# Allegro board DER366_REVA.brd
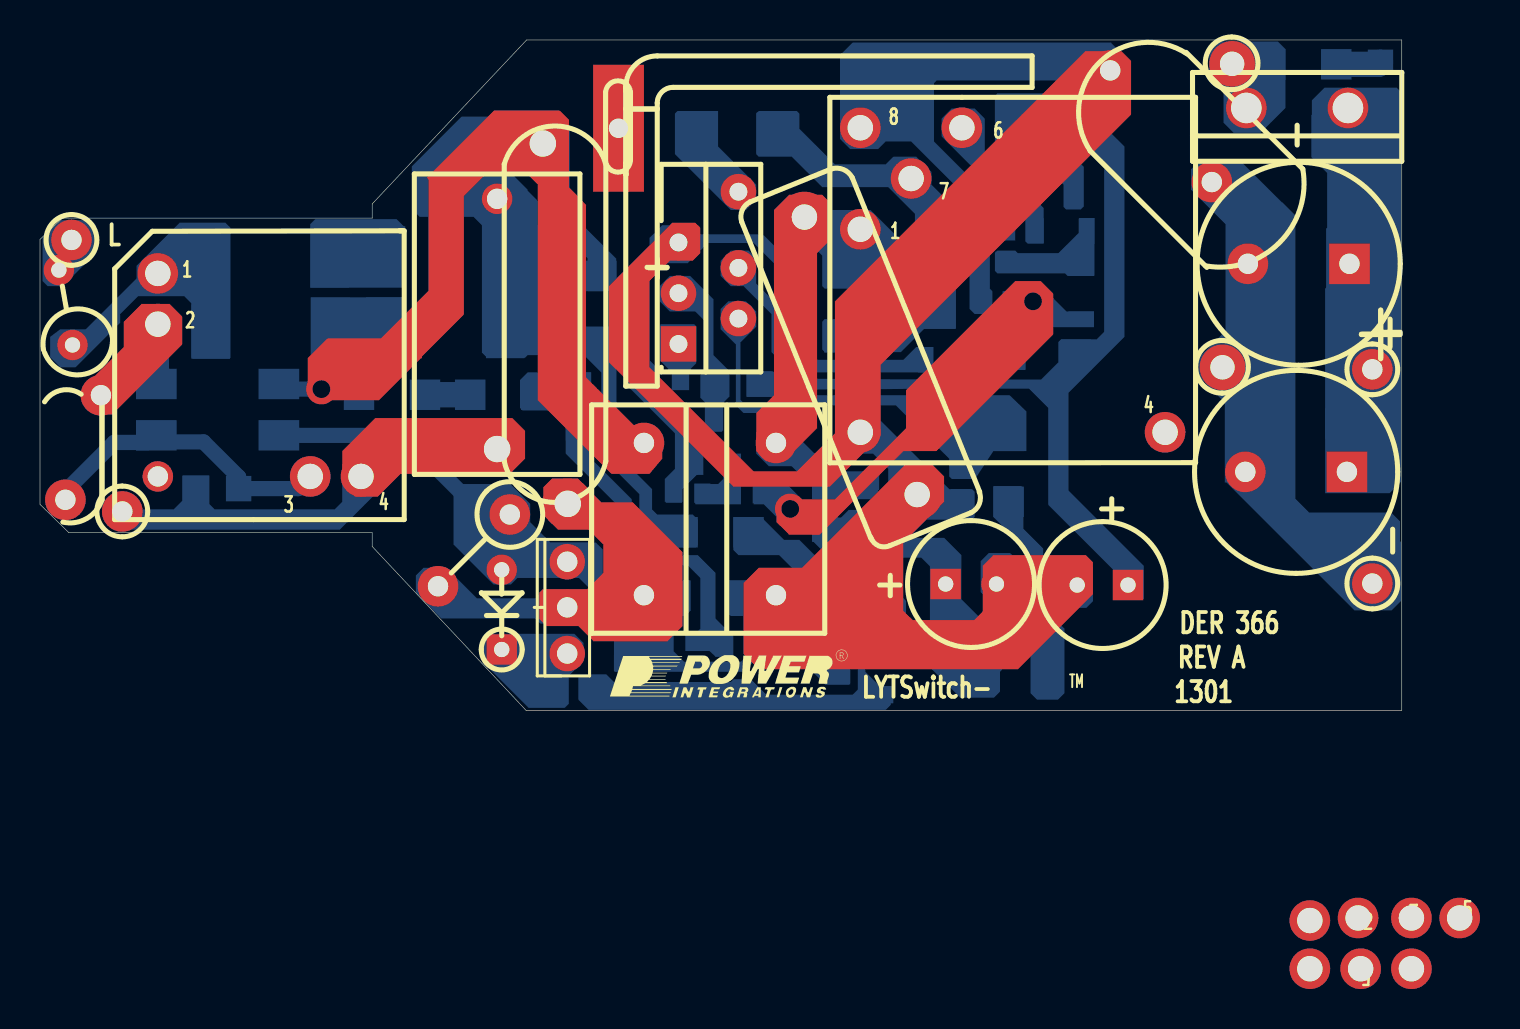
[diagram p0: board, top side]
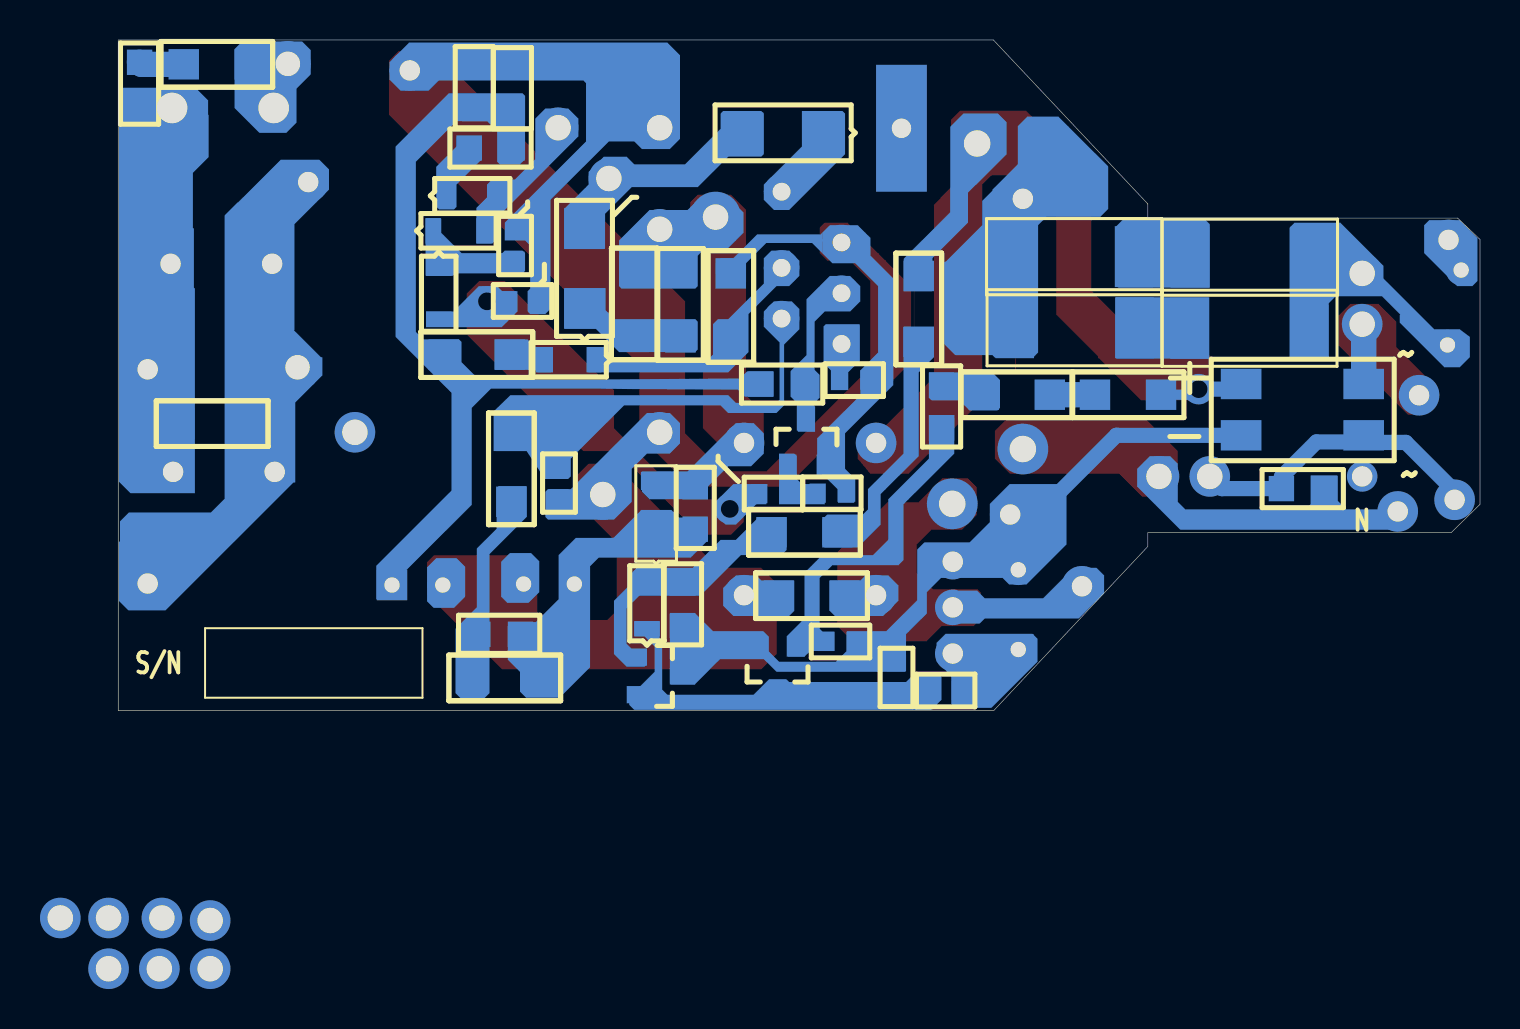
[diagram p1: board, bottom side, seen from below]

Outline 68.1 x 33.55 mm; copper layers: TOP, BOTTOM. Coordinates in mm from the lower left corner of the outline.
Outline path: 0,23.57 1.12,24.64 16.61,24.64 16.61,25.35 24.33,33.55 68.1,33.55 68.1,0 24.31,0 16.61,8.2 16.61,8.89 1.45,8.89 0,10.31 0,23.57

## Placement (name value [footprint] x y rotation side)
BR1  B10S-G  [PISMSOIC4]  5.82 13.77 90 bottom
C1  220 nF  [PI_NP_XCAP_RAD550X330LS493D040]  22.86 13.08 90 top
C2  47 pF  [PISMC0805]  26.92 16.28 270 bottom
C3  10 nF  [PISMC0603]  29.18 0.94 90 bottom
C4  120 nF  [PINPCR730X200LS590D40]  25.76 27.33 270 top
C5  220 nF  [PINPCAPRAD730X230590050]  38.23 24.69 292.1 top
C6  2.2 uF  [PIPOLCAPCYLD250LS100030]  45.29 6.32 0 top
C7  2.2 nF  [PISMC1206]  39.98 21.97 270 bottom
C8  47 uF  [PISMC1206]  37.47 18.57 90 bottom
C9  56 uF  [PIPOLCAPCYLD250LS100030]  54.41 6.27 180 top
C10  10 nF  [PISMC0603]  33.12 10.87 180 bottom
C11  100 nF  [PISMC0805]  48.39 30.07 90 bottom
C12  100 nF  [PISMC0603]  48.26 22.56 90 bottom
C13  100 pF  [PISMC0805]  67.03 32.44 270 bottom
C14  330 uF  [PIPOLCAPCYLD400LS200040]  65.48 22.35 180 top
C15  330 uF  [PIPOLCAPCYLD400LS200040]  65.35 11.94 180 top
C16  47 pF  [PISMC0805]  47.98 3.81 0 bottom
CY1  470 pF  [PINPCAPRAD394X275394030]  53.52 32.03 315 top
D1  BAV21WS-7-F  [PISMSOD323]  41.66 4.09 90 bottom
D2  DFLU1400-7  [PISMDDFLR120012]  41.2 8.84 270 bottom
D3  US1J  [PISMDSMA]  44.78 20.12 90 bottom
D4  US1D  [PISMDSMA]  32.84 28.91 0 bottom
D5  BAV16WS-7-F  [PISMSOD323]  44.3 17.55 0 bottom
D6  BAV21WS-7-F  [PISMSOD323]  51.66 25.76 180 bottom
D7  BAV21WS-7-F  [PISMSOD323]  52.35 24 180 bottom
D8  BYW29-200  [PIDVT0220ACREVA]  60.33 30.15 0 top
F1  5 A  [PI_V_AXIAL_160LS150D030]  1.63 18.29 100.3 top
FL1  PCB Terminal 22 AWG  [PI_HOLE_22AWG]  59.61 32.36 0 top
FL2  PCB Terminal 22 AWG  [PI_HOLE_22AWG]  59.13 17.17 0 top
HS1  HEATSINK,FAB, eSIP WITH BRKT, DER350, PI CUST  [PI_HSK_DER350_ESIP]  29.29 16.23 0 top
L1  RM5  [PI_BOBBIN_RM5_6P_CLP]  5.89 21.87 180 top
L2  5 mH  [PIIND4P615X420LS350X270040]  30.2 13.36 0 top
NOREF  -  []  0 10.31 0 top
NOREF#2  -  []  -224.79 -136.63 0 top
NOREF#3  -  []  68.1 0 90 top
NOREF#4  -  []  -146.97 62.39 0 top
NOREF#5  -  []  28.5 0.63 0 top
Q1  MMBT3906  [PISMSOT23132]  42.16 0.79 270 bottom
Q2  MMBT4401LT1G  [PISMSOT23132]  36.07 3.2 0 bottom
Q3  IRFU320PBF  [PI_TO251AA_123]  26.37 2.87 90 top
Q4  MMBT3904  [PISMSOT23132]  32.74 12.29 180 bottom
R1  510  [PISMR2512]  14.5 22.68 180 bottom
R2  510  [PISMR2512]  23.29 22.71 180 bottom
R3  12 k  [PISMR0805]  7.8 11.1 0 bottom
R4  1 M  [PISMR1206]  28.07 18.44 90 bottom
R5  1 M  [PISMR1206]  35.43 8.92 180 bottom
R6  2.4 M  [PISMR0805]  39.88 6.38 270 bottom
R7  162 k  [PISMR1206]  15.95 15.8 0 bottom
R8  162 k  [PISMR1206]  21.51 15.8 0 bottom
R9  30.1 k  [PISMR0603]  32.69 3.45 180 bottom
R10  15  [PISMR0603]  26.01 0.99 0 bottom
R11  100  [PI12WVRESD180LS150D040]  23.5 9.8 225 top
R12  47 k  [PISMR1206]  35.08 5.74 180 bottom
R13  510 k  [PISMR0805]  39.24 11.2 270 bottom
R14  2.00 M  [PISMR1206]  47.12 1.63 0 bottom
R15  2.00 M  [PISMR1206]  48.44 10.44 90 bottom
R16  49.9 k  [PISMR0603]  46.05 12.09 270 bottom
R17  200 k  [PISMR1206]  42.29 18.69 90 bottom
R18  49.9 k  [PISMR0603]  32 16.54 180 bottom
R19  3 k  [PISMR1206]  48.51 17.81 0 bottom
R20  196 k  [PISMR0805]  33.83 16.33 0 bottom
R21  20 k  [PISMR0805]  50.29 30.12 90 bottom
R22  39  [PISMR0805]  50.55 28.14 180 bottom
R23  10  [PISMR0603]  34.62 10.85 0 bottom
R24  1 k  [PISMR0603]  48.59 20.5 180 bottom
R25  30  [PISMR1206]  64.82 32.33 180 bottom
R26  20 k  [PISMR1206]  65.05 14.35 180 bottom
R27  510  [PISMR2512]  14.53 19.13 180 bottom
R28  510  [PISMR2512]  23.27 19.15 180 bottom
RV1  250 Vac  [PIDISC350X160LS210X140040]  2.69 16.56 270 top
T1  RM7/I  [PI_BOBBIN_RM7_8P_CLP]  41.02 24.08 0 top
TP1  CON1  [PITPKEYSTONE100X100]  1.57 23.55 0 top
TP2  CON1  [PITPKEYSTONE100X100]  4.11 9.96 0 top
TP3  CON1  [PITPKEYSTONE100X100]  66.62 17.07 0 top
TP4  CON1  [PITPKEYSTONE100X100]  66.62 6.35 0 top
U1  LYT4314E  [PIICESIP76TH]  31.93 18.34 90 top
VR1  1N5245B-T  [PIDV200X080X030DO35]  23.09 3.05 90 top
VR2  MMSZ5257BS-7-F  [PISMSOD323]  52.07 22.12 270 bottom

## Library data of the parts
BR1 = DIODE BRIDGE_~~+-
C1 = CAP NP: alternate symbols: (pinpcaprad550x395490030horz)
C2-C5 C7 C8 C10-C13 C16 CY1 = CAP NP
C6 C9 = CAP POL: alternate symbols: (pipolcapcyld250ls100030h)
C14 C15 = CAP POL: alternate symbols: (pipolcapcyld400ls200040800h)
D1-D8 = DIODE
F1 = FUSE
FL1 FL2 = TERM_1Pin
HS1 = HS-PI_CUSTOM1
L1 = BRM6_6P_CLP
L2 = INDUCTOR_4P_revB
Q1 = PNP_BEC
Q2 Q4 = NPN_BEC
Q3 = FET_N_GDS
R1-R10 R12-R25 R27 R28 = R
R11 = R: alternate symbols: (pi12wvresd180ls200d040,pi12wvresd180ls250d040,pi12wresd180ls675d040)
R26 = R: tolerance: 5%
RV1 = VARISTOR
T1 = BRM7_8P_CLP
TP1-TP4 = TESTPOINT
U1 = LNK40X_eSIP
VR1 = DIODE_ZENER: alternate symbols: (pidax375x070030do35)
VR2 = DIODE_ZENER

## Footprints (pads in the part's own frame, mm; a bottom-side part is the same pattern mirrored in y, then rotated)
PI12WVRESD180LS150D040
  round 2.032 hole 1.016: 1(0,0) 2(5.08,0)
PI_BOBBIN_RM5_6P_CLP
  round 2.032 hole 1.27: 1(0,0) 2(0,2.54) 3(-7.62,10.16) 4(-10.16,10.16) 5(-57.607,34.798) 6(-60.147,34.798) CLP1(-62.687,34.798)
  round 1.524 hole 1.016: CLP2(0,10.16)
PI_BOBBIN_RM7_8P_CLP
  round 2.032 hole 1.27: 1(0,0) 2(29.972,-34.468) 3(24.892,-34.468) 4(15.24,-10.16) 5(22.479,-34.595) 6(5.08,5.08) 7(2.54,2.54) 8(0,5.08) CLP1(0,-10.16) CLP2(27.559,-34.468)
PI_HOLE_22AWG
  round 2.286 hole 1.219: 1(0,0)
PI_HSK_DER350_ESIP
  rect 2.54x6.35 hole 0.965: 1(-0.356,12.903)
PI_NP_XCAP_RAD550X330LS493D040
  round 2.54 hole 1.321: 1(0,0)
  round 1.524 hole 1.016: 2(12.522,0)
PI_TO251AA_123
  round 1.778 hole 1.016: 1(-0.025,0) 2(2.286,0) 3(4.572,0)
PI_V_AXIAL_160LS150D030
  round 1.524 hole 0.762: 1(0,0) 2(3.81,0)
PIDISC350X160LS210X140040
  round 2.032 hole 1.016: 1(0.787,0.356) 2(6.02,-1.422)
PIDV200X080X030DO35
  rect 1.524x1.524 hole 0.762: 1(0,0)
  round 1.524 hole 0.762: 2(3.988,0)
PIDVT0220ACREVA
  round 2.032 hole 1.524: 1(5.08,0) 2(0,0)
PIICESIP76TH
  rect 1.778x1.778 hole 0.889: 1(0,0)
  round 1.778 hole 0.889: 2(1.27,-2.997) 3(2.54,0) 4(3.81,-2.997) 5(5.08,0) 7(7.62,-2.997)
PIIND4P615X420LS350X270040
  round 2.032 hole 1.016: 1(0,-7.595) 2(6.604,-7.595) 3(0,0.025) 4(6.604,0.025)
PINPCAPRAD394X275394030
  round 2.032 hole 1.016: 1(0,0) 2(7.543,-0.359)
PINPCAPRAD730X230590050
  round 2.54 hole 1.27: 1(0,0) 2(14.986,0)
PINPCR730X200LS590D40
  round 2.54 hole 1.321: 1(-1.041,-0.61) 2(16.993,0.635)
PIPOLCAPCYLD250LS100030
  rect 1.524x1.524 hole 0.762: 1(0,0)
  round 1.524 hole 0.762: 2(2.54,0)
PIPOLCAPCYLD400LS200040
  rect 2.032x2.032 hole 1.016: 1(0,0)
  round 2.032 hole 1.016: 2(5.08,0)
PISMC0603
  rect 0.813x0.965 smd: 1(0,0) 2(1.422,0)
PISMC0805
  rect 1.27x1.27 smd: 1(0,0) 2(2.134,0)
PISMC1206
  rect 1.524x1.524 smd: 1(0,0) 2(3.302,0)
PISMDDFLR120012
  rect 2.286x1.524 smd: 1(-0.025,0)
  rect 0.914x1.524 smd: 2(-2.642,0)
PISMDSMA
  rect 2.032x2.032 smd: 1(0,0) 2(4.013,0)
PISMR0603
  rect 0.813x0.965 smd: 1(0,0) 2(1.422,0)
PISMR0805
  rect 1.27x1.27 smd: 1(0,0) 2(2.134,0)
PISMR1206
  rect 1.524x1.524 smd: 1(0,0) 2(3.302,0)
PISMR2512
  rect 1.93x3.048 smd: 1(0,0) 2(5.994,0)
PISMSOD323
  rect 0.762x1.27 smd: 1(0,0) 2(2.54,0)
PISMSOIC4
  rect 1.524x2.032 smd: 1(0,0) 2(2.571,0) 3(2.571,6.129) 4(0,6.129)
PISMSOT23132
  rect 0.864x1.016 smd: 1(-1.88,0) 2(0,0)
  rect 0.864x1.27 smd: 3(-0.94,2.286)
PITPKEYSTONE100X100
  round 2.032 hole 1.016: 1(0,0)

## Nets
BULK+: C5.1 C7.1 D2.2 L2.4 R13.1 R17.2 T1.1
BULK-: C5.2 C6.2 C8.2 C9.2 C10.2 C11.2 C12.2 CY1.1 L2.2 Q4.2(EMITTER) R12.1 R16.2 R18.2 R21.2 R24.2 T1.8 T1.CLP1 U1.5(S)
N2034910: C14.2 C15.2 CY1.2 FL2.1 R26.2 TP4.1
N2960943: C4.2 L2.1 Q3.2(D) R11.2 R12.2
N2960957: Q3.1(G) R10.1 VR1.1
N3477441: C9.1 C11.1 R19.2 R20.2 R21.1 R22.2
N3478377: C8.1 D5.1 U1.4(BP)
N3479119: C13.2 C14.1 C15.1 D8.1 R26.1 TP3.1
N3481544: C6.1 C16.1 D2.1 R13.2 R14.1
N3482634: R15.2 R16.1 U1.2(V)
N3538375: BR1.3 C4.1 L2.3 R4.2 R7.1
N3564395: BR1.4 C3.2 Q1.3(COLLECTOR) Q2.2(EMITTER) Q3.3(S) R6.2 R9.2 R11.1 VR1.2
N3568268: C1.1 L1.4 R3.1 TP2.1
N3576797: BR1.2 L1.2 RV1.1
N3617192: D4.1 U1.7(D)
N3617220: D3.2 D4.2 T1.7
N3617246: C7.2 D3.1 R17.1
N3624850: R18.1 U1.1(R)
N3624949: Q4.3(COLLECTOR) R20.1 U1.3(FB)
N3631334: D8.2 FL1.1 R25.2
N3631358: C13.1 R25.1
N3634006: C10.1 Q4.1(BASE) R23.1
N3634524: R23.2 R24.1 VR2.2
N3634757: C12.1 D7.1 VR2.1
N3672532: BR1.1 L1.3 R3.2 RV1.2
N3672946: F1.1 L1.1 R1.2 R27.2
N3675846: C3.1 D1.1 Q1.2(EMITTER) Q2.3(COLLECTOR) R10.2
N3676738: D1.2 Q1.1(BASE) R5.1 R6.1
N3678831: D5.2 R19.1
N3689416: F1.2 TP1.1
N3689420: R1.1 R2.2
N3689424: C1.2 R2.1 R28.1
N3690239: R4.1 R5.2
N3694128: R7.2 R8.1
N3694132: C2.1 R8.2
N3694136: C2.2 Q2.1(BASE) R9.1
N3695980: C16.2 R14.2 R15.1
N3696337: D6.2 D7.2 T1.6
N3706359: D6.1 R22.1
N3724230: R27.1 R28.2

Pads without a net: HS1 1; L1 5 6 CLP1 CLP2; T1 2 3 4 5 CLP2

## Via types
v1: diameter 1.524, hole 0.889, TOP to BOTTOM, 5 vias

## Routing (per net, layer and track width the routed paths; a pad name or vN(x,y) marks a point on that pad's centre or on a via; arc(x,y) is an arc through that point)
BULK+: length 12.9
  BOTTOM w0.127: C7.1 42.29,21.97 R17.2 42.29,22.81 T1.1 38.53,24.08 ; L2.4 37.19,13.39 39.24,11.33 R13.1 39.52,11.48 D2.2
BULK-: length 59.6
  TOP w0.508: T1.CLP1 41.02,13.74
  BOTTOM w0.127: R16.2 44.09,10.67 43.69,11.07 43.69,11.25 T1.CLP1 ; 32.44,23.52 34.34,23.52 34.35,23.53 35.5,23.53 35.52,23.51 35.95,23.51 37.47,22 C8.2 ; C10.2 31.7,11.15 32.74,12.19 Q4.2 32.74,13.51 30.58,15.67 R18.2 30.48,16.41 29.72,17.17 29.72,21.21 v1(31.93,23.42) ; CY1.1 53.29,32.26 R21.2 50.24,32.21 C11.2 43.1,32.21 41.02,30.12 T1.8 43.36,29.16 48.26,24.26 C12.2 47.55,23.98 47.17,23.6 R24.2 ; R12.1 36.78,5.74 L2.2
  BOTTOM w0.381: v1(31.93,23.42) 32,23.42 ; 32,23.42 32.26,23.42 32.49,23.65 ; 32,23.42 32.26,23.67 32.41,23.52 32.42,23.53 32.44,23.52
  BOTTOM w0.508: v1(31.93,23.42) 32.18,23.67 32.26,23.67
N2034910: length 11.9
  BOTTOM w0.508: C15.2 61.7,10.52 ; FL2.1 60.88,17.17 61.32,16.74 61.32,14.78 R26.2 61.75,14.45
  BOTTOM w1.27: C14.2 60.4,24.64 CY1.2
N2960943: length 8.5
  BOTTOM w0.127: R11.2 20.18,6.21 21.26,5.13 25.58,5.13 Q3.2 ; 31.78,5.74 30.23,5.74 v1(30.2,5.77)
N2960957: length 5.9
  BOTTOM w0.127: VR1.1 23.24,2.9 Q3.1 ; R10.1 26.01,2.49 Q3.1 ; Q3.1 26.09,3.33
N3477441: length 35.5
  BOTTOM w0.127: 53.47,19.43 53.47,28.04 51.38,30.12 R21.1 48.44,30.12 C11.1 48.39,27.97 R22.2 ; R20.2 50.34,16.33 R19.2
  BOTTOM w1.27: R19.2 51.82,17.22 50.7,16.1
N3478377: length 12.3
  BOTTOM w0.127: D5.1 44.14,17.5 43.41,17.5 43.21,17.3 38.38,17.3 37.47,18.21 C8.1 37.34,18.69 37.34,19.58 34.92,22 34.92,22.15
N3479119: length 11.4
  BOTTOM w1.27: C13.2 65.56,30.3 D8.1 65.41,20.45
N3481544: length 9.7
  BOTTOM w0.127: R14.1 47.98,2.49 C16.1 47.75,3.58 47.09,3.58 45.29,5.38 C6.1 ; 41.83,8.86 D2.1 39.34,8.86 R13.2
N3482634: length 22.3
  BOTTOM w0.127: R15.2 48.34,13.64 48.24,13.64 48.19,13.59 ; R15.2 47.7,13.74 R16.1 45.97,12.17 ; R15.2 46.66,15.52 37.78,15.52 37.34,15.07 35.27,15.07 34.9,15.44 34.9,17.15 34.92,17.17 34.92,19.61
N3538375: length 10.2
  TOP w0.127: 24.64,28.88 23.09,28.88
  TOP w0.508: 29.69,13.39 L2.3
  TOP w1.27: 24.64,28.88 C4.1
  BOTTOM w0.508: 27.28,23.42 27.64,23.06 27.64,21.74 R4.2 ; R7.1 14.35,15.8 v1(14.07,16.08) ; C4.1 25.96,27.99
  BOTTOM w0.762: v1(14.07,16.08) 12.2,16.08 BR1.3
N3564395: length 38.7
  BOTTOM w0.127: 39.88,4.09 38.99,3.2 Q2.2 35.05,2.18 30.35,2.18 30.18,2.36 ; 39.88,4.09 Q1.3 ; 39.88,4.09 R6.2 ; Q3.3 27.91,5.89 27.91,5.41 29.18,4.14 C3.2 30.18,2.36 ; Q3.3 26.75,7.49 ; Q3.3 23.55,7.49 23.5,7.44 ; 30.18,2.36 R9.2 ; VR1.2 23.5,7.44 ; 23.5,7.44 R11.1
  BOTTOM w0.762: BR1.4 18.19,13.77 21.29,10.67
N3568268: length 16.3
  BOTTOM w0.127: TP2.1 4.17,9.96 4.75,9.37 ; TP2.1 4.47,9.6 6.93,9.6 7.8,10.46 8.64,9.63 14.76,9.63 16.05,10.92 L1.4 ; TP2.1 4.11,9.91 4.57,9.45
  BOTTOM w0.508: R3.1 7.8,10.46
N3576797: length 3
  BOTTOM w1.27: BR1.2 5.82,19.25 L1.2
N3617192: length 3.9
  BOTTOM w0.127: D4.1 32.84,27.89 34.77,25.96 34.92,25.96
N3617220: length 10.8
  BOTTOM w0.127: D3.2 44.91,24.21 43.56,25.55 T1.7 39.14,26.62 D4.2
N3617246: length 5.3
  BOTTOM w0.127: C7.2 R17.1 42.67,18.69 43.94,19.96 D3.1
N3624850: length 1.8
  BOTTOM w0.127: U1.1 31.95,18.31 31.95,16.59 R18.1
N3624949: length 7.4
  BOTTOM w0.127: Q4.3 33.83,14.73 R20.1 33.43,16.74 33.43,19.79 32.33,20.88 U1.3
N3631334: length 4.4
  BOTTOM w1.27: 59.64,32.33 FL1.1 ; 59.64,32.33 R25.2 ; 59.64,32.33 60.33,31.65 D8.2
N3631358: length 2.3
  BOTTOM w1.27: R25.1 66.93,32.33 C13.1
N3634006: length 3
  BOTTOM w0.127: Q4.1 R23.1 33.17,10.85 C10.1
N3634524: length 2.9
  BOTTOM w0.127: v1(37.52,10.08) 36.75,10.85 R23.2 ; R24.1 48.62,20.47 v1(49.66,20.47)
N3634757: length 6.3
  BOTTOM w0.127: VR2.1 52.17,23.7 ; 52.17,23.7 D7.1 ; 52.17,23.7 51.03,22.56 C12.1
N3672532: length 15.5
  BOTTOM w0.762: L1.3 12.9,11.1 R3.2 9.93,11.68 8.18,13.44 6.15,13.44 BR1.1 5.46,13.41 3.71,13.41 1.27,10.97 RV1.2
N3672946: length 9.9
  BOTTOM w0.127: F1.1 2.39,18.36 L1.1 6.32,22.3
  BOTTOM w1.27: R1.2 8.51,19.15 R27.2
N3675846: length 18.6
  BOTTOM w0.127: 27.84,0.94 C3.1 35.1,0.94 Q2.3 35.43,0.91 35.94,0.41 41.78,0.41 Q1.2 41.15,1.8 41.15,3.33 41.66,3.84 D1.1
N3678831: length 0.3
  BOTTOM w0.127: 46.99,17.81 D5.2
N3689416: length 1.8
  BOTTOM w0.127: TP1.1 1.57,22.67 F1.2
N3689424: length 4.6
  BOTTOM w0.127: 23.14,25.32 C1.2
  BOTTOM w1.27: R2.1 23.22,18.82 R28.1
N3690239: length 11.8
  BOTTOM w0.127: R4.1 28.32,18.19 28.32,12.85 30.23,10.95 30.23,9.86 31.17,8.92 R5.2
N3694128: length 2.3
  BOTTOM w1.27: R8.1 R7.2
N3694136: length 6.1
  BOTTOM w0.127: Q2.1 33.93,3.45 R9.1 ; 29.21,10.57 26.92,12.85 C2.2
N3695980: length 9.6
  BOTTOM w0.127: R15.1 48.44,9.35 49.91,7.87 49.91,4.01 C16.2 50.42,3.51 R14.2
N3696337: length 6.9
  BOTTOM w0.127: T1.6 46.61,28.65 46.61,27.84 48.49,25.96 48.92,25.96 D6.2 49.73,25.15 D7.2
N3706359: length 2.9
  BOTTOM w0.127: D6.1 51.66,27.03 R22.1
N3724230: length 2.7
  BOTTOM w1.27: R27.1 16.87,19.13 R28.2

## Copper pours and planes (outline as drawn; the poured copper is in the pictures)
BULK+ on TOP (solid shape): 39.5,25.43 39.5,23.52 38.86,22.89 38.86,14.12 37.21,12.47 36.32,12.47 35.81,12.98 35.81,14.88 36.7,15.77 36.7,25.04 37.47,25.81 39.12,25.81
BULK+ on BOTTOM (solid shape): 39.62,11.96 41.91,11.96 41.91,10.95 41.53,10.57 38.61,10.57 38.61,11.2 37.59,12.22 36.45,12.22 35.81,12.85 35.81,13.87 36.32,14.38 37.21,14.38
BULK+ on BOTTOM (solid shape): 39.62,25.04 41.53,25.04 43.05,23.52 43.05,21.23 42.93,21.11 39.24,21.11 39.12,21.23 39.12,22.76 38.73,23.14 37.59,23.14 36.83,23.9 36.83,24.92 37.59,25.68 38.99,25.68
BULK- on TOP (solid shape): 54.56,32.51 54.56,29.82 42.04,17.3 42.04,13.74 39.5,11.2 34.67,11.2 28.45,17.42 28.45,21.23 31.62,24.41 32.77,24.41 33.02,24.16 33.02,22.89 32.64,22.5 31.5,22.5 30.48,21.49 30.48,17.17 35.69,11.96 37.85,11.96 39.75,13.87 39.75,20.47 52.27,32.99 54.08,32.99
BULK- on TOP (solid shape): 45.21,11.71 45.21,10.44 43.17,8.39 43.17,4.99 43.64,4.52 46.71,4.52 47.14,4.95 47.14,7.24 47.65,7.75 47.65,7.77 52.3,7.77 52.65,7.42 52.65,5.82 48.9,2.06 35.94,2.06 35.18,2.82 35.18,6.38 35.94,7.14 38.1,7.14 43.31,12.34 44.58,12.34
BULK- on BOTTOM (solid shape): 37.85,6.12 37.85,5.23 37.34,4.72 34.54,4.72 34.29,4.98 34.29,6.5 35.94,6.5 36.2,6.76 37.21,6.76
BULK- on BOTTOM (solid shape): 32.97,23.83 36.14,23.83 37.34,22.63 37.97,22.63 38.23,22.38 38.23,21.87 37.72,21.36 36.83,21.36 36.7,21.49 36.7,22.38 35.69,23.39 33.4,23.39 32.89,22.89 32.89,23.9
BULK- on BOTTOM (solid shape): 45.47,11.07 46.61,11.07 46.74,10.95 46.74,9.68 46.61,9.55 43.31,9.55 42.42,10.44 42.42,12.09 41.66,12.85 40.51,12.85 40.01,13.36 40.01,14.38 40.51,14.88 41.66,14.88
BULK- on BOTTOM (solid shape): 32.89,23.9 32.89,22.89 32.38,22.38 31.24,22.38 30.1,21.23 30.1,17.91 30.99,17.02 30.99,15.77 33.15,13.61 33.15,12.09 32.13,11.07 32.13,10.44 31.24,10.44 31.24,11.58 31.75,12.09 31.75,13.87 29.34,16.28 29.34,21.62 30.48,22.76 30.48,23.65 31.11,24.28 32.51,24.28
BULK- on BOTTOM (solid shape): 53.57,33.4 54.53,32.44 54.53,31.57 53.98,31.01 52.58,31.01 52.07,31.52 44.83,31.52 44.7,31.39 44.7,28.47 48.77,24.41 48.77,23.52 47.75,23.52 47.5,23.27 47.5,21.11 47.62,20.98 47.62,19.96 47.5,19.84 46.74,19.84 46.48,20.09 46.48,25.55 43.56,28.47 42.29,28.47 41.91,28.09 40.51,28.09 40.01,28.6 40.01,32.79 40.64,33.43 53.57,33.43
Net_1 on BOTTOM (solid shape): 48.95,7.44 48.95,5.69 48.64,5.38 47.57,5.38 47.04,5.92 47.04,7.47 47.45,7.87 48.51,7.87
Net_1 on BOTTOM (solid shape): 52.65,7.16 52.65,5.46 52.32,5.13 51.31,5.13 50.75,5.69 50.75,7.19 51.18,7.62 52.2,7.62
Net_5 on BOTTOM (solid shape): 2.79,24.28 2.79,22.89 1.14,21.23 0.38,21.23 0.13,21.49 0.13,23.65 1.02,24.54 2.54,24.54
N2034910 on BOTTOM (solid shape): 62.1,25.43 62.13,25.43 62.78,24.78 62.78,10.59 63.46,9.91 67.56,9.91 68.01,9.46 68.01,8.47 68.07,8.41 68.07,5.49 67.59,5 65.74,5 59.33,11.4 59.25,11.4 59.25,15.41 57.89,16.76 57.89,17.68 57.96,17.68 59.31,19.02 59.28,19.05 59.28,24.33 57.56,26.06 57.56,27.08 58.04,27.56 59.97,27.56
N2960943 on TOP (solid shape): 28.07,10.41 29.64,10.41 32.13,7.92 32.13,4.22 31.37,3.45 27.69,3.45 26.92,4.22 25.32,4.22 24.97,4.57 24.97,5.89 25.15,6.07 27.36,6.07 28.17,6.88 28.17,8.31 27.43,9.04 25.91,9.04 25.17,9.78 25.17,11.18 25.6,11.61 26.9,11.61
N2960943 on BOTTOM (solid shape): 30.99,6.5 32.51,6.5 32.51,4.98 32.26,4.72 29.84,4.72 29.08,5.49 29.08,6.25 29.59,6.76 30.73,6.76
N2960943 on BOTTOM (solid shape): 21.84,5.61 24.77,5.61 25.15,5.99 26.04,5.99 26.54,5.49 26.54,4.85 26.04,4.34 25.02,4.34 24.77,4.6 20.07,4.6 18.8,5.87 18.8,6.76 19.18,7.14 20.32,7.14
N2960957 on BOTTOM (solid shape): 27.18,3.38 27.18,2.46 26.44,1.73 26.44,0.33 26.24,0.13 24.43,0.13 22.12,2.44 22.12,3.58 22.38,3.84 26.72,3.84
N3477441 on BOTTOM (solid shape): 54.23,28.22 54.23,18.69 51.44,15.9 51.44,11 55.19,7.24 55.19,5.56 53.9,5.56 53.72,5.74 53.72,6.99 50.42,10.29 50.42,15.14 49.45,16.1 44.25,16.1 42.21,16.08 37.11,16.05 36.75,15.7 35.33,15.7 35.33,16.97 36.65,16.97 37.01,16.61 44.42,16.56 50.06,16.56 50.93,17.42 50.93,18.44 51.05,18.57 52.83,18.57 53.21,18.95 53.21,27.46 51.18,29.49 49.66,29.49 49.15,28.98 49.15,27.46 49.02,27.33 48.01,27.33 47.75,27.58 47.75,30.76 47.88,30.89 51.56,30.89
N3478377 on BOTTOM (solid shape): 35.81,22.63 35.81,21.36 37.59,19.58 38.1,19.58 38.35,19.33 38.35,17.81 38.61,17.55 43.18,17.55 43.81,18.19 44.58,18.19 44.65,18.11 44.65,16.99 44.58,16.92 37.59,16.92 36.58,17.93 36.58,19.84 35.18,21.23 34.54,21.23 34.04,21.74 34.04,22.5 34.54,23.01 35.43,23.01
N3479119 on BOTTOM (solid shape): 68.07,30.94 68.07,11.46 67.49,10.87 64.26,10.87 64.26,21.11 64.31,21.16 64.31,24.1 64.36,24.16 64.36,26.9 63.58,27.69 63.58,29.79 63.6,29.82 63.6,30.53 64.24,31.17 67.84,31.17
N3481544 on BOTTOM (solid shape): 43.33,8.64 45.21,8.64 46.08,7.77 46.08,5.56 47.22,4.42 48.41,4.42 48.62,4.22 48.62,2.54 48.01,1.93 48.01,0.94 47.7,0.63 46.02,0.63 44.5,2.16 44.5,7.21 44.07,7.65 39.47,7.65 38.61,8.51 38.61,9.58 38.68,9.65 40.06,9.65 40.44,10.03 41.94,10.03
N3482634 on BOTTOM (solid shape): 35.81,19.96 35.81,19.2 35.03,18.41 35.03,15.54 35.18,15.39 37.21,15.39 37.59,15.77 48.49,15.77 49.33,14.96 49.33,12.98 47.68,12.98 46.76,11.58 45.59,11.58 45.47,11.71 45.47,12.6 42.8,15.27 37.97,15.27 37.59,14.88 35.18,14.88 34.8,15.27 34.8,18.31 34.04,19.08 34.04,20.09 34.42,20.47 35.31,20.47
N3538375 on TOP (solid shape): 26.45,29.55 26.45,26.17 26.97,25.65 26.97,25.63 27.32,25.29 27.3,25.27 27.3,16.66 29.84,14.12 30.61,14.12 31.11,13.61 31.11,12.6 30.48,11.84 28.57,11.84 24.89,15.52 24.89,26.31 24.43,26.77 22.23,26.77 21.2,25.74 21.2,19.81 19.1,17.72 19.1,17.63 19.05,17.63 16.94,15.52 14,15.52 13.39,16.13 13.39,17.63 14.38,18.62 17.04,18.62 19.43,21.01 19.43,26.57 19.34,26.66 22.71,30.02 25.98,30.02
N3538375 on BOTTOM (solid shape): 26.49,29.21 26.49,24.93 28.82,22.61 28.82,20.99 28.83,20.98 27.41,20.98 27.41,22.61 25.6,24.41 25.6,25.91 23.67,27.84 23.67,29.44 24.1,29.87 25.83,29.87
N3564395 on BOTTOM (solid shape): 24.51,10.34 24.51,9.42 25.53,8.41 27.79,8.41 28.14,8.05 28.14,5.51 29.69,3.96 31.65,3.96 31.67,3.94 31.67,2.97 32.21,2.44 35.05,2.44 35.56,2.95 35.56,3.68 35.84,3.96 38.35,3.96 39.27,4.88 40.49,4.88 40.51,4.85 40.51,1.37 40.44,1.3 39.27,1.3 38,2.57 35.81,2.57 35.18,1.93 28.75,1.93 28.7,1.98 28.7,3.81 27.66,4.85 27.66,5.92 26.95,6.63 23.88,6.63 23.55,6.3 22.68,6.3 20.68,8.31 20.68,11.28 20.73,11.33 23.52,11.33
N3568268 on TOP (solid shape): 24.26,14 24.26,12.6 23.5,11.84 18.03,11.84 16.89,10.69 15.75,10.69 15.11,11.33 15.11,12.98 16.76,14.63 23.62,14.63
N3568268 on BOTTOM (solid shape): 17.14,12.09 17.14,11.2 14.99,9.04 4.06,9.04 4.06,10.06 6.68,10.06 7.11,10.49 7.11,11.73 7.14,11.76 8.46,11.76 8.47,11.75 8.47,10.33 8.74,10.06 14.73,10.06 15.11,10.44 15.11,12.34 15.49,12.73 16.51,12.73
N3576797 on TOP (solid shape): 7.11,19.71 7.11,18.31 3.61,14.81 2.74,14.81 2.74,14.83 2.11,15.47 2.11,16.13 2.51,16.54 2.54,16.54 4.19,18.19 4.19,19.46 5.08,20.35 6.48,20.35
N3617192 on BOTTOM (solid shape): 33.91,28.22 35.81,26.31 35.81,25.55 35.31,25.04 34.54,25.04 31.75,27.84 31.75,29.87 31.88,30 33.91,30
N3617220 on BOTTOM (solid shape): 37.97,29.87 37.97,29.11 39.75,27.33 42.29,27.33 42.67,27.71 43.81,27.71 44.58,26.95 44.58,26.31 45.8,25.1 45.8,23.09 43.79,23.09 43.75,23.13 43.75,24.85 42.42,26.19 39.12,26.19 37.59,27.71 35.94,27.71 35.81,27.84 35.81,29.87 35.94,30 37.85,30
N3617246 on BOTTOM (solid shape): 45.8,21.11 45.8,19.13 45.77,19.1 44.22,19.1 43.05,17.93 39.24,17.93 39.12,18.06 39.12,19.46 39.24,19.58 43.28,19.58 43.73,20.03 43.73,21.12 43.74,21.13 45.77,21.13
N3624850 on BOTTOM (solid shape): 32.82,19.23 32.82,17.37 32.46,17.02 32.46,16.03 31.62,16.03 31.6,16.05 31.6,16.92 31.01,17.5 31.01,19.3 31.04,19.33 32.72,19.33
N3624949 on BOTTOM (solid shape): 33.68,20.57 33.68,17.78 34.47,16.99 34.47,15.7 34.16,15.39 34.16,14 33.27,14 33.27,15.39 33.02,15.65 33.02,16.79 33.27,17.04 33.27,19.46 32.77,19.96 31.5,19.96 30.99,20.47 30.99,21.23 31.5,21.74 32.51,21.74
N3631334 on BOTTOM (solid shape): 62.28,33.1 62.28,30.15 61.04,28.91 59.69,28.91 59.18,29.41 59.18,31.12 58.47,31.83 58.47,33.05 58.9,33.48 61.9,33.48
N3634006 on BOTTOM (solid shape): 35.05,10.31 32.77,10.31 32.77,11.33 33.91,11.33 34.16,11.58 34.16,12.73 34.29,12.85 35.05,12.85
N3634524 on TOP (solid shape): 50.67,20.85 50.67,18.82 44.83,12.98 43.18,12.98 38.99,8.79 37.47,8.79 36.83,9.42 36.83,10.31 37.34,10.82 37.59,10.82 37.85,10.57 39.75,10.57 43.31,14.12 43.31,16.03 48.77,21.49 50.04,21.49
N3634524 on BOTTOM (solid shape): 38.23,10.44 38.23,9.8 37.72,9.3 37.21,9.3 36.2,10.31 35.69,10.31 35.69,11.33 37.34,11.33
N3634524 on BOTTOM (solid shape): 51.33,19.96 52.7,19.96 52.7,19.46 52.68,19.46 52.7,19.43 52.7,19.18 48.92,19.18 48.13,19.96 48.13,20.98 48.9,20.98 49.15,21.23 50.06,21.23
N3634757 on BOTTOM (solid shape): 52.73,21.77 52.7,21.74 51.38,21.74 51.26,21.87 47.88,21.87 47.75,22 47.75,22.89 47.88,23.01 48.77,23.01 48.9,22.89 50.93,22.89 51.94,23.9 51.94,24.61 51.97,24.64 52.73,24.64
N3672946 on BOTTOM (solid shape): 9.53,24.16 9.53,17.65 9.47,17.6 7.65,17.6 7.57,17.68 7.57,20.29 7.59,20.32 7.59,20.35 7.21,20.73 4.9,20.73 3.99,19.81 4.01,19.79 4.01,19.41 1.78,17.17 1.02,17.17 0.51,17.68 0.51,18.69 1.02,19.08 2.29,19.08 4.83,21.62 4.83,22.25 6.99,24.41 9.27,24.41
N3675846 on BOTTOM (solid shape): 42.29,3.71 41.78,3.71 41.27,3.2 41.27,1.93 42.04,1.17 42.16,1.17 42.55,0.79 42.55,0.28 42.29,0.03 27.43,0.03 26.92,0.53 26.92,1.68 27.05,1.8 28.32,1.8 28.7,1.42 34.54,1.42 34.67,1.55 35.56,1.55 36.32,0.79 40.64,0.79 40.89,1.04 40.89,3.45 41.02,3.58 41.02,4.47 42.29,4.47
N3676738 on BOTTOM (solid shape): 37.21,8.53 37.97,8.53 39.37,7.14 42.16,7.14 42.42,6.88 42.42,6.38 43.31,5.49 43.31,2.82 42.67,2.18 41.78,2.18 41.66,2.31 41.66,2.95 41.78,3.07 42.42,3.07 42.67,3.33 42.67,5.11 42.04,5.74 38.99,5.74 36.96,7.77 34.92,7.77 34.67,8.03 34.67,9.68 36.07,9.68
N3678831 on BOTTOM (solid shape): 49.28,17.04 47.24,17.04 47.12,16.92 46.35,16.92 46.35,18.19 47.24,18.19 47.62,18.57 49.28,18.57
N3689420 on BOTTOM (solid shape): 18.21,24.21 18.21,21.29 18.08,21.16 13.51,21.16 13.51,24.33 13.77,24.59 17.83,24.59
N3689424 on BOTTOM (solid shape): 23.11,29.24 23.11,27.33 24.38,26.06 24.38,26.01 24.89,25.5 24.89,24.28 26.72,22.45 26.8,22.45 26.8,18.34 26.24,17.78 24.38,17.78 24.26,17.65 22.35,17.65 22.1,17.91 22.1,24.28 21.68,24.7 18.99,24.7 18.59,25.1 18.59,27.23 21.08,29.72 22.63,29.72
N3690239 on BOTTOM (solid shape): 28.83,12.85 30.61,11.07 30.61,10.06 30.86,9.8 32.64,9.8 32.89,9.55 32.89,8.28 32.77,8.15 31.11,8.15 29.97,9.3 29.97,10.82 28.07,12.73 28.07,16.92 27.3,17.68 27.3,19.2 28.83,19.2
N3694132 on BOTTOM (solid shape): 27.56,15.65 27.43,15.52 26.04,15.52 25.53,15.01 24.13,15.01 24,15.14 24,16.54 24.38,16.92 27.56,16.92
N3694136 on BOTTOM (solid shape): 27.56,12.6 29.59,10.57 29.59,8.53 30.35,7.77 32.89,7.77 33.78,6.88 33.78,4.6 34.67,3.71 34.67,2.69 33.78,2.69 33.48,2.97 32.28,2.97 32.28,3.94 32.87,3.94 33.02,4.09 33.02,6.63 32.38,7.26 29.08,7.26 28.83,7.52 28.83,10.31 26.29,12.85 26.29,14.63 26.42,14.76 27.56,14.76
N3695980 on BOTTOM (solid shape): 49.17,11.13 49.17,9.09 50.16,8.1 50.16,5.16 51.23,4.09 51.23,0.86 50.9,0.53 49.86,0.53 49.53,0.86 49.53,7.82 47.68,9.68 47.68,11.23 49.07,11.23
N3696337 on BOTTOM (solid shape): 47.24,29.62 47.24,27.58 48.26,26.57 49.4,26.57 49.66,26.31 49.66,25.68 50.19,25.15 50.19,23.37 49.38,23.37 49.28,23.47 49.28,24.54 45.09,28.73 45.09,29.62 45.59,30.12 46.74,30.12
N3706359 on BOTTOM (solid shape): 51.18,28.22 52.2,27.2 52.2,25.22 52.04,25.07 51.31,25.07 51.18,25.2 51.18,26.31 49.91,27.58 49.91,28.73 51.18,28.73
N3724230 on BOTTOM (solid shape): 18.24,20.65 18.24,17.65 18.19,17.6 13.56,17.6 13.54,17.63 13.54,20.68 18.21,20.68

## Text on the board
Ref Des/Silkscreen Bottom: N | S/N
Ref Des/Silkscreen Top: TM | L | LYTSwitch- | 1301 | REV A | DER 366
PEN17: PLEASE DELETE THESE PINS | 3 SLOTS | 13   MATERIAL FR4 COPPER 2oz THICKNESS 0.031"
User.5: FIGURE | SIZE | 30.0 | 35.0 | 38.0 | 40.0 | 48.0 | 50.0 | 52.0 | 60.0 | DRILL CHART: TOP to BOTTOM | ALL UNITS ARE IN MILS | PLATED | QTY | 10 | 6 | 5 | 1 | 19 | 2 | 18
